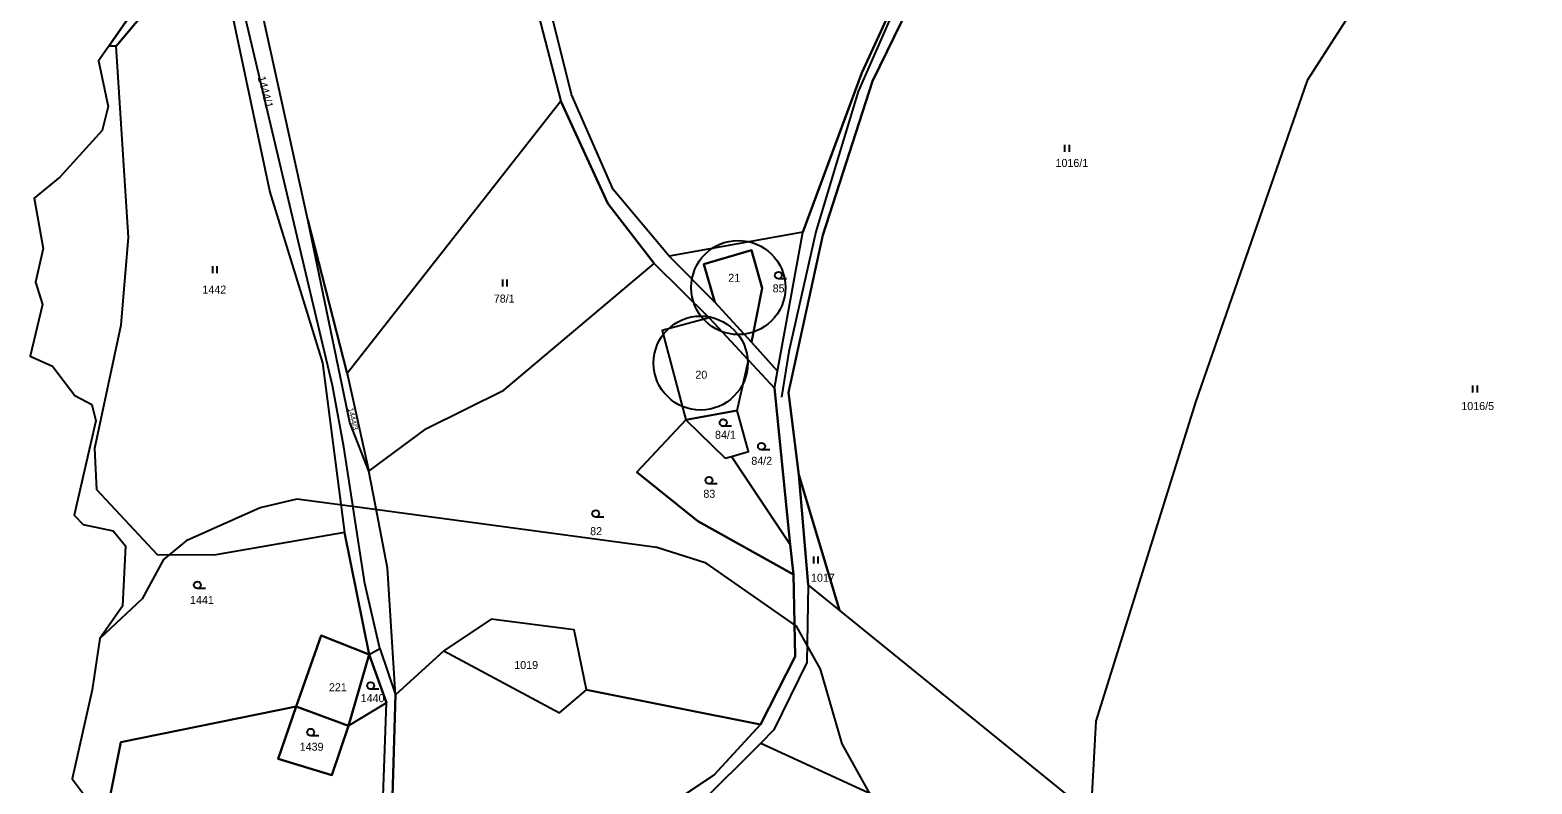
# Model space of a CAD drawing. Extents: x -588699 to -585793, y -1060280 to -1056731.
# Drawn here: x -588415.7 to -588096.7, y -1058756.3 to -1058596 of the extents above; entities that cross this region are included whole.
import ezdxf

# ---------------------------------------------------------------- set-up
doc = ezdxf.new("R2010")
doc.units = 0
for name, color, linetype in [('Druh pozemku', 7, 'Continuous'), ('Neřešené', 7, 'Continuous'), ('Parcela nároku', 7, 'Continuous'), ('Stavby', 7, 'Continuous'), ('Vnitřní obvod', 7, 'Continuous'), ('Vnější hranice převzatá', 7, 'Continuous'), ('Vnější obvod_k šeření', 7, 'Continuous')]:
    doc.layers.add(name, color=color, linetype=linetype)

msp = doc.modelspace()

# ---------------------------------------------------------------- linework, layer by layer
at = {"layer": 'Druh pozemku'}
for p, q in [((-588195.93, -1058620.39), (-588195.93, -1058621.89)), ((-588194.91, -1058621.89), (-588194.91, -1058620.39)), ((-588376.97, -1058646.15), (-588376.97, -1058647.65)), ((-588375.95, -1058647.65), (-588375.95, -1058646.15)), ((-588315.36, -1058648.99), (-588315.36, -1058650.49)), ((-588314.33, -1058650.49), (-588314.33, -1058648.99)), ((-588254.99, -1058648.89), (-588256.74, -1058648.89)), ((-588109.27, -1058671.52), (-588109.27, -1058673.02)), ((-588108.24, -1058673.02), (-588108.24, -1058671.52)), ((-588266.71, -1058680.22), (-588268.46, -1058680.22)), ((-588258.56, -1058685.23), (-588260.31, -1058685.23)), ((-588269.73, -1058692.45), (-588271.48, -1058692.45)), ((-588293.79, -1058699.55), (-588295.54, -1058699.55)), ((-588249.31, -1058707.92), (-588249.31, -1058709.42)), ((-588248.29, -1058709.42), (-588248.29, -1058707.92)), ((-588378.4, -1058714.71), (-588380.15, -1058714.71)), ((-588341.6, -1058736.12), (-588343.35, -1058736.12)), ((-588354.33, -1058746), (-588356.08, -1058746))]:
    msp.add_line(p, q, dxfattribs=at)
for centre in [(-588256.74, -1058648.14), (-588268.46, -1058679.47), (-588260.31, -1058684.48), (-588271.48, -1058691.7), (-588295.54, -1058698.8), (-588380.15, -1058713.96), (-588343.35, -1058735.37), (-588356.08, -1058745.25)]:
    msp.add_circle(centre, 0.75, dxfattribs=at)
at = {"layer": 'Neřešené'}
msp.add_lwpolyline([(-588343.66, -1058728.74), (-588353.88, -1058724.67), (-588359.14, -1058739.8), (-588348.06, -1058743.89)], close=True, dxfattribs=at)
at = {"layer": 'Parcela nároku'}
for points in [[(-588262.95, -1058496.95), (-588256.04, -1058490.3), (-588231.73, -1058483.49), (-588208.11, -1058487.86), (-588214.97, -1058497.94), (-588188.92, -1058517.82), (-588196.26, -1058524.58), (-588208.14, -1058541.13), (-588224.97, -1058574.45), (-588238.98, -1058605.06), (-588251.51, -1058638.95), (-588279.94, -1058644.03), (-588291.86, -1058629.85), (-588300.68, -1058609.7), (-588310.57, -1058569.75), (-588313.12, -1058564.65)], [(-588313.12, -1058564.65), (-588313.16, -1058551.02), (-588312.54, -1058543.42), (-588311.91, -1058535.6), (-588302.55, -1058507.33), (-588296.31, -1058492.71), (-588301.9, -1058498.09), (-588314.84, -1058533.3), (-588316.42, -1058551.04), (-588315.12, -1058565.82), (-588313.43, -1058570.64), (-588302.97, -1058611.13), (-588292.99, -1058632.88), (-588283.09, -1058645.63), (-588271.45, -1058657.16), (-588263.1, -1058666.16), (-588257.57, -1058672.12), (-588256.91, -1058668.49), (-588262.48, -1058662.36), (-588270.26, -1058653.8), (-588279.94, -1058644.03), (-588291.86, -1058629.85), (-588300.68, -1058609.7), (-588310.57, -1058569.75)], [(-588353.94, -1058538.87), (-588324.19, -1058519.78), (-588301.9, -1058498.09), (-588314.84, -1058533.3), (-588316.42, -1058551.04), (-588315.12, -1058565.82), (-588313.43, -1058570.64), (-588302.97, -1058611.13), (-588348.33, -1058668.99), (-588356.72, -1058636.32), (-588372.54, -1058564.1), (-588368.33, -1058556.18)], [(-588160.71, -1058571.53), (-588133.04, -1058556.28), (-588119.64, -1058548.89), (-588109.86, -1058524.53), (-588108.4, -1058531.35), (-588109.84, -1058534.93), (-588112.84, -1058542.38), (-588131.02, -1058585.83), (-588144.44, -1058606.7), (-588168.14, -1058675.06), (-588189.32, -1058742.9), (-588190.21, -1058759.8), (-588191.27, -1058761.91), (-588243.79, -1058719.3), (-588252.4, -1058690.54), (-588254.57, -1058673), (-588247.32, -1058639.55), (-588236.75, -1058606.83), (-588215.17, -1058562.54)], [(-588189.32, -1058742.9), (-588190.21, -1058759.8), (-588172.56, -1058777.54), (-588159.73, -1058806.34), (-588132.18, -1058821.5), (-588109.1, -1058827.66), (-588088.15, -1058840.59), (-588084.85, -1058785.48), (-588068.73, -1058707.6), (-588040.36, -1058604.95), (-588044.66, -1058596.24), (-588112.84, -1058542.38), (-588131.02, -1058585.83), (-588144.44, -1058606.7), (-588168.14, -1058675.06)], [(-588377.36, -1058566.31), (-588377.37, -1058570.85), (-588364.75, -1058630.46), (-588353.56, -1058666.69), (-588348.88, -1058702.79), (-588343.66, -1058728.74), (-588341.37, -1058727.45), (-588338.07, -1058737.33), (-588339.76, -1058710.4), (-588342.33, -1058697.03), (-588343.74, -1058689.76), (-588347.77, -1058679.4), (-588356.72, -1058636.32), (-588372.54, -1058564.1), (-588375.1, -1058553.89)], [(-588381.33, -1058580.18), (-588377.37, -1058570.85), (-588364.75, -1058630.46), (-588353.56, -1058666.69), (-588348.88, -1058702.79), (-588376.64, -1058707.58), (-588388.63, -1058707.51), (-588401.53, -1058693.71), (-588401.95, -1058684.88), (-588396.37, -1058658.64), (-588394.82, -1058640.06), (-588397.37, -1058599.4)], [(-588389, -1058585.03), (-588386.77, -1058578.66), (-588381.33, -1058580.18), (-588397.37, -1058599.4), (-588398.97, -1058599.37)], [(-588283.09, -1058645.63), (-588292.99, -1058632.88), (-588302.97, -1058611.13), (-588348.33, -1058668.99), (-588343.74, -1058689.76), (-588331.49, -1058680.68), (-588315.09, -1058672.56)], [(-588348.33, -1058668.99), (-588343.74, -1058689.76), (-588347.77, -1058679.4), (-588356.72, -1058636.32)], [(-588260.17, -1058650.84), (-588262.48, -1058662.36), (-588256.91, -1058668.49), (-588251.51, -1058638.95), (-588279.94, -1058644.03), (-588270.26, -1058653.8), (-588272.6, -1058645.73), (-588262.43, -1058642.76)], [(-588262.43, -1058642.76), (-588272.6, -1058645.73), (-588270.26, -1058653.8), (-588262.48, -1058662.36), (-588260.17, -1058650.84)], [(-588331.49, -1058680.68), (-588315.09, -1058672.56), (-588283.09, -1058645.63), (-588271.45, -1058657.16), (-588281.45, -1058659.82), (-588276.38, -1058678.84), (-588286.81, -1058689.98), (-588273.88, -1058700.42), (-588253.56, -1058711.74), (-588253.15, -1058729.16), (-588260.53, -1058743.61), (-588297.53, -1058736.25), (-588300.1, -1058723.51), (-588317.75, -1058721.19), (-588327.82, -1058727.96), (-588338.07, -1058737.33), (-588339.76, -1058710.4), (-588342.33, -1058697.03), (-588343.74, -1058689.76)], [(-588271.45, -1058657.16), (-588281.45, -1058659.82), (-588276.38, -1058678.84), (-588265.46, -1058676.83), (-588263.1, -1058666.16)], [(-588265.46, -1058676.83), (-588263.1, -1058666.16), (-588257.57, -1058672.12), (-588254.22, -1058705.35), (-588266.71, -1058686.64), (-588263.07, -1058685.6)], [(-588268.06, -1058687.02), (-588266.71, -1058686.64), (-588254.22, -1058705.35), (-588253.56, -1058711.74), (-588273.88, -1058700.42), (-588286.81, -1058689.98), (-588276.38, -1058678.84)], [(-588263.07, -1058685.6), (-588265.46, -1058676.83), (-588276.38, -1058678.84), (-588268.06, -1058687.02), (-588266.71, -1058686.64)], [(-588252.4, -1058690.54), (-588243.79, -1058719.3), (-588250.43, -1058713.91)], [(-588250.43, -1058713.91), (-588250.68, -1058730.43), (-588257.72, -1058744.78), (-588260.49, -1058747.55), (-588235.98, -1058758.87), (-588211.07, -1058801.26), (-588191.27, -1058761.91), (-588243.79, -1058719.3)], [(-588317.75, -1058721.19), (-588327.82, -1058727.96), (-588303.2, -1058741.14), (-588297.53, -1058736.25), (-588300.1, -1058723.51)], [(-588359.14, -1058739.8), (-588353.88, -1058724.67), (-588343.66, -1058728.74), (-588348.06, -1058743.89)], [(-588342.31, -1058804.33), (-588339.95, -1058739.02), (-588343.66, -1058728.74), (-588341.37, -1058727.45), (-588338.07, -1058737.33), (-588340.02, -1058804.51), (-588343.49, -1058830.48), (-588350.5, -1058865.29), (-588355.15, -1058897.34), (-588370.1, -1058950.25), (-588373.71, -1058949.83), (-588361.28, -1058911.03), (-588357.52, -1058896.76), (-588353.19, -1058861.08), (-588344.73, -1058830.3)], [(-588348.06, -1058743.89), (-588343.66, -1058728.74), (-588339.95, -1058739.02)], [(-588303.2, -1058741.14), (-588297.53, -1058736.25), (-588260.53, -1058743.61), (-588270.38, -1058754.32), (-588276.16, -1058758.24), (-588280.94, -1058765.67), (-588295.8, -1058801.58), (-588305.48, -1058815.25), (-588338.72, -1058812.26), (-588340.02, -1058804.51), (-588338.07, -1058737.33), (-588327.82, -1058727.96)], [(-588414.77, -1058823.03), (-588406.35, -1058827.67), (-588399.22, -1058834.97), (-588389.69, -1058838.62), (-588382.84, -1058828.28), (-588374.67, -1058820.58), (-588365.72, -1058823.51), (-588348.67, -1058829.72), (-588344.73, -1058830.3), (-588342.31, -1058804.33), (-588339.95, -1058739.02), (-588348.06, -1058743.89), (-588351.62, -1058754.39), (-588363, -1058750.94), (-588359.14, -1058739.8), (-588396.41, -1058747.35), (-588403.57, -1058783.34), (-588404.52, -1058793.53), (-588411.78, -1058808.18)], [(-588359.14, -1058739.8), (-588363, -1058750.94), (-588351.62, -1058754.39), (-588348.06, -1058743.89)], [(-588273.5, -1058760.57), (-588260.49, -1058747.55), (-588235.98, -1058758.87), (-588211.07, -1058801.26), (-588234.01, -1058786.34), (-588246.49, -1058779.65), (-588260.4, -1058767.79)]]:
    msp.add_lwpolyline(points, close=True, dxfattribs=at)
for points in [[(-588215.17, -1058562.54), (-588236.75, -1058606.83), (-588247.32, -1058639.55), (-588254.57, -1058673), (-588252.4, -1058690.54), (-588250.43, -1058713.91), (-588250.68, -1058730.43), (-588257.72, -1058744.78), (-588260.49, -1058747.55), (-588273.5, -1058760.57)], [(-588276.16, -1058758.24), (-588270.38, -1058754.32), (-588260.53, -1058743.61), (-588253.15, -1058729.16), (-588253.56, -1058711.74), (-588254.22, -1058705.35), (-588257.57, -1058672.12), (-588256.91, -1058668.49), (-588251.51, -1058638.95), (-588238.98, -1058605.06), (-588224.97, -1058574.45)], [(-588403.57, -1058783.34), (-588396.41, -1058747.35), (-588359.14, -1058739.8), (-588353.88, -1058724.67), (-588343.66, -1058728.74), (-588348.88, -1058702.79), (-588376.64, -1058707.58), (-588388.63, -1058707.51), (-588401.53, -1058693.71), (-588401.95, -1058684.88), (-588396.37, -1058658.64), (-588394.82, -1058640.06), (-588397.37, -1058599.4), (-588398.97, -1058599.37), (-588401.15, -1058602.5), (-588399.09, -1058612.24), (-588400.41, -1058617.31), (-588409.27, -1058627.19), (-588414.79, -1058631.7), (-588412.91, -1058642.41), (-588414.51, -1058649.6), (-588413.06, -1058654.34), (-588415.7, -1058665.32), (-588410.94, -1058667.41), (-588406.22, -1058673.67), (-588402.6, -1058675.58), (-588401.7, -1058679.03), (-588406.36, -1058699.13), (-588404.4, -1058701.06), (-588398.01, -1058702.47), (-588395.4, -1058705.66), (-588396.03, -1058718.44), (-588400.84, -1058725.3), (-588402.5, -1058736.26), (-588406.72, -1058755.13), (-588404.44, -1058758.28)]]:
    msp.add_lwpolyline(points, dxfattribs=at)
at = {"layer": 'Stavby'}
for centre in [(-588265.25, -1058650.72), (-588273.25, -1058666.77)]:
    msp.add_circle(centre, 10, dxfattribs=at)
at = {"layer": 'Vnitřní obvod'}
for points in [[(-588226.41, -1058578.26), (-588234.44, -1058596.76), (-588239.76, -1058609.02), (-588244.58, -1058624.91), (-588248.8, -1058638.84), (-588254.55, -1058664.35), (-588256.06, -1058674.03)], [(-588341.37, -1058727.45), (-588344.61, -1058713.65), (-588349.02, -1058684.58), (-588351.48, -1058671.54), (-588355.85, -1058653.02), (-588371.42, -1058587.04)]]:
    msp.add_lwpolyline(points, dxfattribs=at)
at = {"layer": 'Vnější hranice převzatá'}
for p, q in [((-588389, -1058585.03), (-588398.97, -1058599.37)), ((-588398.97, -1058599.37), (-588401.15, -1058602.5)), ((-588401.15, -1058602.5), (-588399.09, -1058612.24)), ((-588399.09, -1058612.24), (-588400.41, -1058617.31)), ((-588400.41, -1058617.31), (-588409.27, -1058627.19)), ((-588409.27, -1058627.19), (-588414.79, -1058631.7)), ((-588414.79, -1058631.7), (-588412.91, -1058642.41)), ((-588412.91, -1058642.41), (-588414.51, -1058649.6)), ((-588414.51, -1058649.6), (-588413.06, -1058654.34)), ((-588413.06, -1058654.34), (-588415.7, -1058665.32)), ((-588415.7, -1058665.32), (-588410.94, -1058667.41)), ((-588410.94, -1058667.41), (-588406.22, -1058673.67)), ((-588406.22, -1058673.67), (-588402.6, -1058675.58)), ((-588402.6, -1058675.58), (-588401.7, -1058679.03)), ((-588401.7, -1058679.03), (-588406.36, -1058699.13)), ((-588406.36, -1058699.13), (-588404.4, -1058701.06)), ((-588404.4, -1058701.06), (-588398.01, -1058702.47)), ((-588398.01, -1058702.47), (-588395.4, -1058705.66)), ((-588395.4, -1058705.66), (-588396.03, -1058718.44)), ((-588396.03, -1058718.44), (-588400.84, -1058725.3)), ((-588400.84, -1058725.3), (-588402.5, -1058736.26)), ((-588402.5, -1058736.26), (-588406.72, -1058755.13)), ((-588406.72, -1058755.13), (-588404.44, -1058758.28))]:
    msp.add_line(p, q, dxfattribs=at)
at = {"layer": 'Vnější obvod_k šeření'}
msp.add_lwpolyline([(-588091.31, -1058874.05), (-588100.79, -1058867.12), (-588122.75, -1058858.23), (-588143.47, -1058847.7), (-588152.63, -1058841.11), (-588175.11, -1058819.21), (-588191.52, -1058802.34), (-588222.77, -1058776.57), (-588235.38, -1058761.73), (-588243.16, -1058747.73), (-588247.81, -1058731.85), (-588252.9, -1058722.69), (-588272.06, -1058709.29), (-588282.58, -1058705.95), (-588344.03, -1058697.71), (-588359, -1058695.68), (-588366.85, -1058697.58), (-588382.53, -1058704.58), (-588387.37, -1058708.5), (-588391.88, -1058716.87), (-588400.84, -1058725.3)], dxfattribs=at)

# ---------------------------------------------------------------- texts
at = {"layer": 'Parcela nároku'}
for s, height, rotation, p in [('1444/1', 1.7, 284.5345, (-588367.38, -1058606.01)), ('1444/3', 1.14, 283.3554, (-588348.16, -1058676.45))]:
    msp.add_text(s, height=height, rotation=rotation, dxfattribs=at).set_placement(p)
for s, p in [('1016/1', (-588197.87, -1058625.08)), ('1442', (-588379.09, -1058652)), ('21', (-588267.38, -1058649.49)), ('85', (-588257.95, -1058651.74)), ('78/1', (-588317.19, -1058653.91)), ('20', (-588274.37, -1058670.1)), ('1016/5', (-588111.67, -1058676.76)), ('84/1', (-588270.2, -1058682.87)), ('84/2', (-588262.49, -1058688.4)), ('83', (-588272.67, -1058695.41)), ('82', (-588296.72, -1058703.36)), ('1017', (-588249.81, -1058713.26)), ('1441', (-588381.72, -1058718)), ('1019', (-588312.84, -1058731.82)), ('221', (-588352.21, -1058736.54)), ('1440', (-588345.47, -1058738.86)), ('1439', (-588358.42, -1058749.19))]:
    msp.add_text(s, height=1.7, dxfattribs=at).set_placement(p)

doc.saveas('drawing.dxf')
